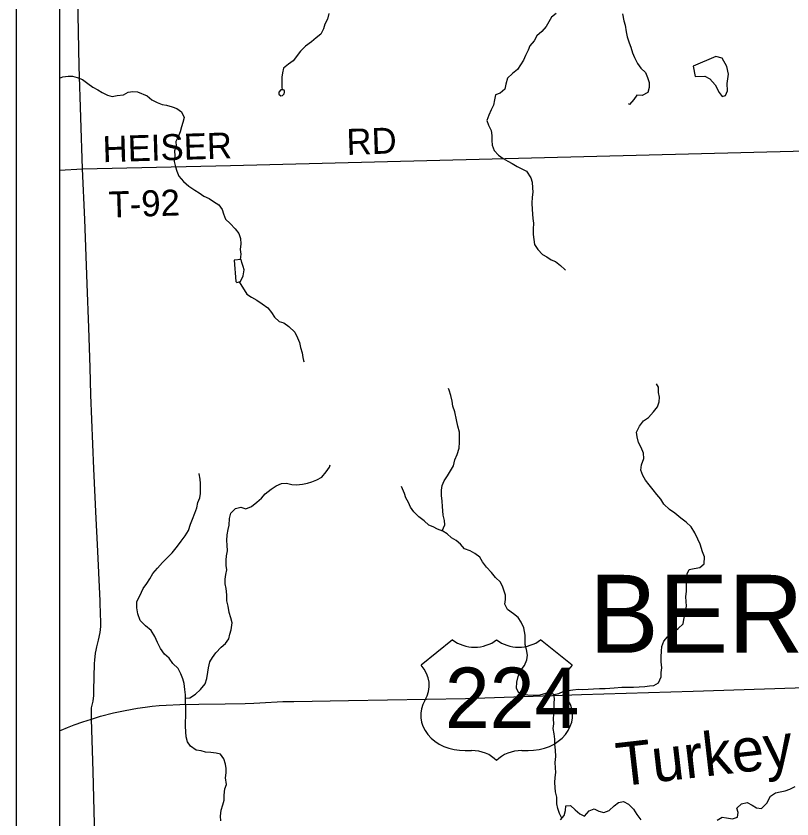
# Model space of a CAD drawing. Extents: x 0 to 34, y 0 to 22.
# Drawn here: x 2.895 to 4.591, y 17.274 to 19.028 of the extents above; entities that cross this region are included whole.
import ezdxf

# ---------------------------------------------------------------- set-up
doc = ezdxf.new("R2010")
doc.units = 0
for name, color, linetype in [('GM_X_Corporation', 7, 'Continuous'), ('GM_X_County_Road', 7, 'Continuous'), ('GM_X_Minor_Lake', 7, 'Continuous'), ('GM_X_Minor_River', 7, 'Continuous'), ('GM_X_Minor_River_Text', 7, 'Continuous'), ('GM_X_Township_Road', 7, 'Continuous'), ('GM_X_Township_Road_Text', 7, 'Continuous'), ('GM_X_Township_Text', 7, 'Continuous'), ('GM_X_US_Location', 7, 'Continuous'), ('GM_X_US_Route', 7, 'Continuous'), ('GM_X_US_Shield', 7, 'Continuous'), ('SH_Data', 7, 'Continuous')]:
    doc.layers.add(name, color=color, linetype=linetype)

msp = doc.modelspace()

# ---------------------------------------------------------------- linework, layer by layer
at = {"layer": 'GM_X_Corporation'}
msp.add_lwpolyline([(7.2872, 17.1772), (7.283, 17.3071), (7.2799, 17.4174), (7.2764, 17.5202), (7.2751, 17.5764), (7.2467, 19.0557), (7.2468, 19.0896), (7.2426, 19.2998), (7.2392, 19.4543), (7.237, 19.6097), (7.2344, 19.7492), (7.2317, 19.8848), (7.2291, 20.0061), (7.2266, 20.122), (7.2254, 20.198), (6.0786, 20.1754), (5.7004, 20.168), (4.9925, 20.1548), (3.1549, 20.1187), (2.9895, 20.1176), (2.9895, 14.989)], dxfattribs=at)
at = {"layer": 'GM_X_County_Road'}
for points in [[(3.0595, 17.4921), (3.0597, 17.5162), (3.061, 17.5224), (3.0633, 17.5313), (3.0647, 17.5434), (3.0648, 17.5549), (3.0662, 17.6127), (3.0666, 17.6212), (3.0673, 17.628), (3.0683, 17.6358), (3.0697, 17.6429), (3.0713, 17.6501), (3.0747, 17.6645), (3.0782, 17.6812), (3.0791, 17.688), (3.0799, 17.694), (3.0801, 17.7), (3.0798, 17.7083), (3.0792, 17.7186), (3.0781, 17.7501), (3.0723, 17.8736), (3.0693, 17.9306), (3.0642, 18.0391), (3.0581, 18.2007), (3.0567, 18.2604), (3.0536, 18.3467), (3.0498, 18.4434), (3.0447, 18.5839), (3.0395, 18.6946), (3.0328, 18.9186), (3.0276, 19.1815)], [(3.0667, 17.2336), (3.0632, 17.3772), (3.0595, 17.4921)]]:
    msp.add_lwpolyline(points, dxfattribs=at)
at = {"layer": 'GM_X_Minor_Lake'}
msp.add_line((4.3745, 18.9188), (4.3793, 18.896), dxfattribs=at)
for points in [[(4.3793, 18.896), (4.4002, 18.897), (4.4113, 18.891), (4.4228, 18.8781), (4.4317, 18.8611), (4.4379, 18.8528), (4.4454, 18.8548), (4.4499, 18.8647), (4.449, 18.8806), (4.4515, 18.9012), (4.4479, 18.9183), (4.4383, 18.9361), (4.4245, 18.9397), (4.3745, 18.9188)], [(3.4781, 18.8671), (3.4736, 18.8671), (3.469, 18.8617), (3.4691, 18.8575), (3.4733, 18.8542), (3.4767, 18.8546), (3.4809, 18.8584), (3.4812, 18.8618)], [(3.4812, 18.8618), (3.4815, 18.8645), (3.4808, 18.8662), (3.4781, 18.8671)], [(3.3753, 18.4482), (3.3773, 18.4463), (3.3852, 18.4482), (3.3908, 18.4608), (3.3934, 18.4734), (3.391, 18.481), (3.3879, 18.4897), (3.3867, 18.4965), (3.3715, 18.4949)], [(3.3715, 18.4949), (3.3753, 18.4482)]]:
    msp.add_lwpolyline(points, dxfattribs=at)
at = {"layer": 'GM_X_Minor_River'}
for points in [[(3.5782, 19.034), (3.5753, 19.0218), (3.5693, 19.0108), (3.5667, 19.0001), (3.5607, 18.989), (3.5509, 18.9806)], [(4.0749, 19.0338), (4.0647, 19.0258), (4.0591, 19.0159), (4.0531, 19.0055), (4.0437, 18.9944), (4.0331, 18.9852), (4.0271, 18.9745), (4.0174, 18.9634), (4.014, 18.9535), (4.0084, 18.9421), (4.0039, 18.9322), (3.9972, 18.9215), (3.9908, 18.9112), (3.9795, 18.9027), (3.9685, 18.8927), (3.9649, 18.8794), (3.963, 18.8687), (3.9529, 18.8599), (3.9426, 18.856), (3.9404, 18.8454), (3.9379, 18.8339), (3.933, 18.8233), (3.9278, 18.8114), (3.9237, 18.8004), (3.9269, 18.7898), (3.9327, 18.778), (3.9343, 18.7674), (3.9348, 18.7564), (3.9352, 18.7465), (3.9399, 18.7347), (3.9491, 18.7242), (3.9594, 18.7167), (3.9694, 18.7114), (3.9789, 18.7062), (3.99, 18.6998), (4, 18.6942), (4.0103, 18.6893), (4.0199, 18.6746), (4.0227, 18.6651), (4.0235, 18.6533), (4.024, 18.6438), (4.0229, 18.6328), (4.0223, 18.6191), (4.0228, 18.6058), (4.0241, 18.5857), (4.0254, 18.5758), (4.0251, 18.5629), (4.0252, 18.5511), (4.0264, 18.5401), (4.0277, 18.5294), (4.0354, 18.5181), (4.0454, 18.5075), (4.0549, 18.5019), (4.0645, 18.4955), (4.074, 18.4918), (4.0844, 18.4835), (4.094, 18.4745), (4.0955, 18.4733)], [(4.2198, 19.0335), (4.223, 19.0176), (4.2261, 19.0081), (4.2278, 18.9936), (4.2302, 18.983), (4.2345, 18.9701), (4.238, 18.9603), (4.2419, 18.9481), (4.2462, 18.9379), (4.2527, 18.925), (4.2601, 18.9141), (4.2704, 18.905), (4.2747, 18.8944), (4.2786, 18.8834), (4.2787, 18.872), (4.2754, 18.8614), (4.2629, 18.8548), (4.2518, 18.8555), (4.2451, 18.8459), (4.2353, 18.8348), (4.2334, 18.8367)], [(3.5509, 18.9806), (3.54, 18.9721), (3.5271, 18.9622), (3.5166, 18.9514), (3.5, 18.9308), (3.4898, 18.9231), (3.4792, 18.9146), (3.4767, 18.904), (3.4752, 18.8945), (3.4753, 18.885), (3.4758, 18.8732), (3.4765, 18.8671)], [(2.9895, 18.8926), (2.9967, 18.8956), (3.0081, 18.8972), (3.018, 18.8969), (3.0283, 18.8943), (3.0398, 18.8898), (3.0513, 18.8808), (3.0624, 18.8729), (3.0731, 18.8673), (3.083, 18.8613), (3.0945, 18.8557), (3.1044, 18.8527), (3.1154, 18.8547), (3.1295, 18.8563), (3.1397, 18.8617), (3.1495, 18.8633), (3.1598, 18.8627), (3.1812, 18.8537), (3.1912, 18.8454), (3.203, 18.8394), (3.2141, 18.8354), (3.2236, 18.8335), (3.2358, 18.8298), (3.2457, 18.8265)], [(3.2457, 18.8265), (3.2561, 18.819), (3.2619, 18.8068), (3.2593, 18.7958), (3.2563, 18.7863), (3.2534, 18.7752), (3.2486, 18.7642), (3.2441, 18.7542), (3.2442, 18.744), (3.2412, 18.7341), (3.2413, 18.7227), (3.2403, 18.7105), (3.2434, 18.6987), (3.2458, 18.6893), (3.2505, 18.6783), (3.2604, 18.667), (3.2723, 18.6564), (3.285, 18.6478), (3.2949, 18.6418), (3.3052, 18.6346), (3.3163, 18.6294), (3.3262, 18.6234), (3.3377, 18.6155), (3.3454, 18.6057), (3.3478, 18.5958), (3.3525, 18.5848), (3.3628, 18.575), (3.3732, 18.5637), (3.3813, 18.5531), (3.3848, 18.5421), (3.3856, 18.5307), (3.3846, 18.5182), (3.3862, 18.5079), (3.3842, 18.4963)], [(3.3825, 18.4476), (3.3988, 18.4206), (3.4091, 18.4138), (3.421, 18.4075), (3.4328, 18.3996), (3.4451, 18.3909), (3.4528, 18.3804), (3.4593, 18.3705), (3.4697, 18.3611), (3.4796, 18.3578), (3.4911, 18.3499), (3.5041, 18.3374), (3.5095, 18.3249), (3.5138, 18.3151), (3.5166, 18.3037), (3.5197, 18.2923), (3.5217, 18.2825), (3.5237, 18.273), (3.5229, 18.2734)], [(3.8256, 17.9034), (3.8315, 17.9166), (3.8307, 17.9261), (3.8283, 17.9375), (3.8271, 17.947), (3.8266, 17.9565), (3.8257, 17.9683), (3.8245, 17.9804), (3.8244, 17.9926), (3.8262, 18.0025), (3.8303, 18.0124), (3.8378, 18.0235), (3.8445, 18.0346), (3.8505, 18.0456), (3.8538, 18.0582), (3.859, 18.0704), (3.8631, 18.0837), (3.8641, 18.0974), (3.8639, 18.1187), (3.8604, 18.132), (3.8572, 18.146), (3.8533, 18.1635), (3.849, 18.1756), (3.8481, 18.1866), (3.845, 18.1992), (3.8415, 18.2109), (3.8395, 18.2143)], [(4.0698, 17.546), (4.0812, 17.548), (4.0922, 17.553), (4.1017, 17.5543), (4.1116, 17.5559), (4.1241, 17.5571), (4.1336, 17.5564), (4.145, 17.5573), (4.1568, 17.5581), (4.1701, 17.559), (4.1819, 17.5587), (4.1926, 17.5595), (4.2021, 17.5604), (4.2188, 17.562), (4.2313, 17.5614), (4.2443, 17.5619), (4.2568, 17.5627), (4.2686, 17.5632), (4.2788, 17.5644), (4.2887, 17.5653), (4.2986, 17.5714), (4.3045, 17.5844), (4.3045, 17.5939), (4.3059, 17.6038), (4.3046, 17.6171), (4.3045, 17.6277), (4.3052, 17.6407), (4.3062, 17.6509), (4.3107, 17.662), (4.3186, 17.6716), (4.3299, 17.6808), (4.342, 17.6896), (4.3526, 17.7), (4.354, 17.7098), (4.3566, 17.7194), (4.358, 17.7289), (4.3598, 17.7384), (4.3594, 17.7487), (4.3585, 17.7593), (4.3599, 17.7715), (4.3602, 17.7836), (4.3597, 17.7988), (4.3615, 17.8091), (4.366, 17.8187), (4.377, 17.821), (4.3891, 17.823), (4.399, 17.8311), (4.3992, 17.8467), (4.3949, 17.8577), (4.3898, 17.8744), (4.3848, 17.885), (4.3782, 17.899), (4.3705, 17.9118), (4.3594, 17.922), (4.3475, 17.9314), (4.3348, 17.9419), (4.323, 17.9498), (4.3103, 17.9619), (4.3038, 17.9725), (4.2953, 17.9827), (4.2869, 17.9933), (4.2784, 18.0042), (4.2703, 18.014), (4.2649, 18.0243), (4.2599, 18.036), (4.262, 18.0478), (4.2665, 18.0615), (4.2664, 18.0729), (4.2606, 18.0854), (4.2551, 18.0964), (4.252, 18.1085), (4.2508, 18.1188), (4.2571, 18.1321), (4.2657, 18.144), (4.2767, 18.1509), (4.288, 18.1632), (4.297, 18.1747), (4.3004, 18.1853), (4.3007, 18.1952), (4.2987, 18.2058), (4.2986, 18.2176), (4.2947, 18.2244)], [(3.2649, 17.5379), (3.2746, 17.5381), (3.2871, 17.5462), (3.2976, 17.5566), (3.3078, 17.5688), (3.3119, 17.5806), (3.314, 17.5947), (3.3151, 17.6042), (3.318, 17.6168), (3.3237, 17.6263), (3.3312, 17.6366), (3.3428, 17.6493), (3.3527, 17.6573), (3.3594, 17.6677), (3.362, 17.6772), (3.365, 17.6867), (3.3667, 17.7023), (3.364, 17.7133), (3.3604, 17.7247), (3.3584, 17.7384), (3.3556, 17.7505), (3.3555, 17.7638), (3.3539, 17.7775), (3.3519, 17.7873), (3.3514, 17.798), (3.3532, 17.8083), (3.355, 17.8182), (3.3538, 17.8276), (3.3541, 17.839), (3.3544, 17.8486), (3.3566, 17.8596), (3.3557, 17.8721), (3.3556, 17.8824), (3.3563, 17.8946), (3.3581, 17.9064), (3.3606, 17.9159), (3.3609, 17.93), (3.3642, 17.9421), (3.374, 17.9521), (3.3862, 17.9549), (3.3968, 17.9515), (3.409, 17.9562), (3.4211, 17.9658), (3.4309, 17.9746), (3.4388, 17.9842), (3.452, 17.9942), (3.4633, 18.0015), (3.4751, 18.0065), (3.4854, 18.0074), (3.4976, 18.0044), (3.5074, 18.0037), (3.5207, 18.005), (3.5318, 18.0077), (3.5412, 18.0108), (3.5522, 18.0151), (3.5628, 18.0209), (3.5722, 18.0324), (3.5794, 18.0423), (3.5808, 18.0476)], [(3.3424, 17.2695), (3.3412, 17.2798), (3.343, 17.2927), (3.3463, 17.3045), (3.3492, 17.3145), (3.3495, 17.3255), (3.3509, 17.3392), (3.3542, 17.3491), (3.3522, 17.3635), (3.3536, 17.3742), (3.3539, 17.3841), (3.352, 17.3935), (3.3488, 17.4049), (3.3415, 17.4151), (3.3316, 17.4177), (3.3202, 17.4188), (3.3087, 17.4194), (3.2992, 17.4224), (3.2882, 17.4238), (3.2759, 17.4325), (3.269, 17.4423), (3.2662, 17.4529), (3.2654, 17.4639), (3.2649, 17.4765), (3.2652, 17.4867), (3.2655, 17.4966), (3.2654, 17.5076), (3.266, 17.5175), (3.2648, 17.5312), (3.265, 17.5449), (3.2638, 17.5567), (3.2618, 17.5699), (3.2594, 17.5798), (3.2547, 17.5908), (3.2486, 17.6025), (3.2374, 17.6135), (3.229, 17.6252), (3.219, 17.6342), (3.2101, 17.6459), (3.2036, 17.6596), (3.1981, 17.6728), (3.1896, 17.6857), (3.1777, 17.6959), (3.1662, 17.7075), (3.1608, 17.7219), (3.1584, 17.7352), (3.1583, 17.7489), (3.165, 17.7615), (3.1725, 17.7772), (3.1807, 17.7882), (3.1867, 17.7982), (3.1935, 17.81), (3.204, 17.8219), (3.2146, 17.8345), (3.2244, 17.8437), (3.2357, 17.8552), (3.2477, 17.8701), (3.2556, 17.8808), (3.2643, 17.8923), (3.2718, 17.9042), (3.2762, 17.9179), (3.2799, 17.9285), (3.2851, 17.9419), (3.29, 17.9537), (3.2921, 17.9655), (3.2962, 17.9758), (3.2977, 17.9853), (3.2976, 17.9956), (3.2979, 18.007), (3.297, 18.0165), (3.295, 18.0279), (3.295, 18.0286)], [(4.0875, 17.2755), (4.0824, 17.2857), (4.0789, 17.2964), (4.0765, 17.3066), (4.0767, 17.3214), (4.0736, 17.3328), (4.0731, 17.3427), (4.0723, 17.3533), (4.0726, 17.364), (4.0744, 17.375), (4.0739, 17.3853), (4.0727, 17.397), (4.0741, 17.4103), (4.0739, 17.4237), (4.0719, 17.4369), (4.0722, 17.448), (4.0706, 17.4597), (4.0686, 17.4711), (4.0704, 17.4818), (4.0695, 17.4924), (4.0702, 17.5027), (4.0709, 17.5152), (4.0711, 17.527), (4.0714, 17.5365), (4.0698, 17.546), (4.0595, 17.5505), (4.0493, 17.5474), (4.0364, 17.5438), (4.0261, 17.5434), (4.0135, 17.544), (4.0037, 17.5447), (3.9926, 17.55), (3.9883, 17.5598), (3.989, 17.5724), (3.9923, 17.5849), (3.9967, 17.5964), (4.0061, 17.609), (4.0113, 17.6212), (4.0124, 17.6315), (4.0104, 17.6444), (4.0076, 17.655), (4.0072, 17.6645), (4.0074, 17.6751), (4.0043, 17.6911), (3.9984, 17.7036), (3.9923, 17.7138), (3.9819, 17.7217), (3.9685, 17.7318), (3.9631, 17.7432), (3.9645, 17.7531), (3.9641, 17.763), (3.9586, 17.7804), (3.9532, 17.791), (3.9424, 17.8012), (3.9336, 17.8125), (3.9225, 17.8242), (3.914, 17.8356), (3.9086, 17.8458), (3.8975, 17.854), (3.8868, 17.8593), (3.8749, 17.8638), (3.8661, 17.8739), (3.8565, 17.8822), (3.8466, 17.8879), (3.837, 17.8965), (3.8271, 17.9029), (3.816, 17.907), (3.8064, 17.9122), (3.7969, 17.916), (3.7865, 17.925), (3.7747, 17.934), (3.7639, 17.945), (3.757, 17.9552), (3.7527, 17.965), (3.7462, 17.9752), (3.7434, 17.9851), (3.7391, 17.9949), (3.7372, 18.0002)], [(4.4267, 17.2714), (4.4381, 17.2776), (4.4476, 17.2761), (4.4605, 17.274), (4.4715, 17.2778), (4.4726, 17.2881), (4.4702, 17.2976), (4.48, 17.3064), (4.4926, 17.3099), (4.5033, 17.3039), (4.5132, 17.2979), (4.5239, 17.2969), (4.5356, 17.3084), (4.5438, 17.3233), (4.5548, 17.331), (4.565, 17.333), (4.5756, 17.3353), (4.5859, 17.3388), (4.5972, 17.3446)], [(4.0848, 17.2721), (4.0923, 17.2816), (4.0953, 17.2923), (4.0963, 17.3026), (4.1066, 17.3034), (4.1169, 17.294), (4.1269, 17.285), (4.1368, 17.2801), (4.147, 17.2912), (4.1584, 17.2958), (4.1687, 17.291), (4.179, 17.288), (4.1907, 17.2919), (4.2017, 17.3023), (4.2115, 17.3096), (4.2221, 17.3119), (4.2336, 17.306), (4.244, 17.295), (4.2517, 17.2837), (4.2601, 17.272)]]:
    msp.add_lwpolyline(points, dxfattribs=at)
at = {"layer": 'GM_X_Township_Road'}
msp.add_line((2.9895, 18.6915), (3.0395, 18.6946), dxfattribs=at)
msp.add_lwpolyline([(3.0395, 18.6946), (3.3635, 18.7014), (5.0505, 18.745)], dxfattribs=at)
at = {"layer": 'GM_X_US_Route'}
for points in [[(3.4145, 17.5268), (3.4274, 17.5272), (3.478, 17.5301), (3.5017, 17.5306), (3.6213, 17.5328), (3.877, 17.5372), (4.1307, 17.5455), (4.3745, 17.5533), (4.6866, 17.5634)], [(2.9895, 17.4665), (2.9928, 17.4679), (3.0069, 17.4739), (3.0214, 17.4796), (3.0407, 17.4863), (3.0595, 17.4921), (3.0793, 17.4981), (3.1077, 17.5053), (3.1328, 17.5104), (3.1602, 17.5155), (3.1769, 17.518), (3.1922, 17.52), (3.2077, 17.5216), (3.2226, 17.5225), (3.2522, 17.5236), (3.2938, 17.5247), (3.3517, 17.5252), (3.3956, 17.5261), (3.4145, 17.5268)]]:
    msp.add_lwpolyline(points, dxfattribs=at)
at = {"layer": 'GM_X_US_Shield'}
for p, q in [((3.8489, 17.6649), (3.7802, 17.61)), ((4.1098, 17.61), (4.0411, 17.6649)), ((3.8763, 17.4232), (3.8901, 17.4232)), ((3.9999, 17.4232), (4.0137, 17.4232))]:
    msp.add_line(p, q, dxfattribs=at)
for centre, major_axis, start_param, end_param in [((3.8969, 17.7042), (-0.0687, 0), 0.795399, 2.346194), ((3.9931, 17.7042), (-0.0687, 0), 0.795399, 2.346194), ((3.7015, 17.5659), (0.0961, 0), 5.838949, 6.894067), ((4.1885, 17.5659), (-0.0961, 0), 5.672304, 6.727422), ((3.8753, 17.5001), (0.0961, 0), 2.702327, 4.723529), ((4.0147, 17.5001), (-0.0961, 0), 1.559657, 3.580859), ((3.8901, 17.3683), (-0.0687, 0), 3.785094, 4.712389), ((3.9999, 17.3683), (-0.0687, 0), 4.712389, 5.639684)]:
    msp.add_ellipse(centre, major_axis=major_axis, ratio=0.8, start_param=start_param, end_param=end_param, dxfattribs=at)
at = {"layer": 'SH_Data'}
msp.add_line((2.8945, 20.8873), (2.8945, 13.8873), dxfattribs=at)

# ---------------------------------------------------------------- texts
at = {"layer": 'GM_X_Minor_River_Text'}
msp.add_text('Turkey', height=0.09473, rotation=6.5592, dxfattribs=at).set_placement((4.2119, 17.3447))
at = {"layer": 'GM_X_Township_Road_Text'}
for s, rotation, p in [('RD', 1.9738, (3.6177, 18.7247)), ('HEISER', 1.7712, (3.0845, 18.7088)), ('T-92', 1.7682, (3.0974, 18.5879))]:
    msp.add_text(s, height=0.05682, rotation=rotation, dxfattribs=at).set_placement(p)
at = {"layer": 'GM_X_Township_Text'}
msp.add_text('BERLIN', height=0.17045, rotation=0, dxfattribs=at).set_placement((4.1472, 17.6368))
at = {"layer": 'GM_X_US_Location'}
for s in ['0', '/']:
    msp.add_text(s, height=0.000189, dxfattribs=at).set_placement((3.9451, 17.5385))
msp.add_text('224', height=0.000189, rotation=0, dxfattribs=at).set_placement((3.8868, 17.4993))
at = {"layer": 'GM_X_US_Shield'}
msp.add_text('224', height=0.13184, dxfattribs=at).set_placement((3.8318, 17.4727))

doc.saveas('drawing.dxf')
